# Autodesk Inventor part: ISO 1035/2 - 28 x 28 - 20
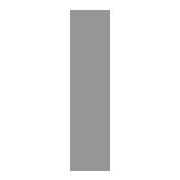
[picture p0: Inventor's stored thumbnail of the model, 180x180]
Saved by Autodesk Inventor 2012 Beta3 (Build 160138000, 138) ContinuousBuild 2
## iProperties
Created: 2010-11
Part Number: ISO 1035/2 - 28 x 28 - 20
Material: Steel, Mild
Description: Hot-rolled steel bars - Part 2: square bars
Document SubType Name: Modeling
Standard: ISO
Designer: Beta-8540w
Standard Revision: First edition 1980-10-15
Standards Organization: ISO
Language: en-US
Size Designation: 28x 28*
Categories: <MemberInstance><Categories><Category DisplayName="Structural Shapes" InternalName="089c4875-fa83-4c05-b084-43b9cc11f5ed" Mnemonic="GRDR"><CategoryParameter Dis
Stock Number: 28x 28*
Density: 7.86 g/cm^3
IsCustomPart: 1
_CCFamilyMember: 180
_CCFamilyDisplayName: ISO 1035/2 - 1980 - Hot-rolled steel bars - Part 2: square bars
_FrameMemberDoc: Frame Member File
_Version: 15.0.0
_GetPNFromCC: 1
G_L: 20.000 mm
G_W: 28.000 mm
G_H: 28.000 mm
Author: Beta-8540w
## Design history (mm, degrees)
node "Start plane"
node "End plane"
sketch "Sketch"
  geometry: L1 (14, -14)-(-14, -14); L2 (-14, -14)-(-14, 14); L3 (-14, 14)-(14, 14); L4 (14, 14)-(14, -14); L5 (-6, 0)-(8, 0); L6 (0, -30)-(0, 40); L7 (0, 54)-(0, -44) reference; L8 (-19.6, 0)-(19.6, 0) reference
  constraints: 12 end point, 2 collinear, 2 parallel, 1 horizontal, 1 perpendicular
  dimensions: "d0" = 28 distance between parallel lines of L3 L1 (= G_W); "d1" = 28 distance between parallel lines of L4 L2 (= G_H); "d4" = 14 distance between parallel lines of L6 L4 (= 0.5 x d1); "d5" = 14 distance between parallel lines of L5 L3 (= 0.5 x d0)
extrude "Body" new body sketch "Sketch" stored distance "d2" = 20 (= G_L); taper "d3" = 0 deg
node "Driven Length"
  sketch "Sketch3"
    geometry: L1 (0, 0)-(10, 0) reference
    constraints: 2 end point, 1 horizontal
  workplane "Work Plane3"
  sketch "Sketch4"
    geometry: L1 (-2, 0)-(12, 0) reference; L2 (-2, 20)-(12, 20) reference
    dimensions: "d9" = 20 distance between parallel lines of L1 L2 (derived)
body "Solid1"
other parameters: "G_W" = 28 [user parameter; used in 1 equation term], "G_H" = 28 [user parameter; used in 1 equation term], "G_L" = 20 (= d9) [user parameter; used in 1 equation term], "G_OFFSET_START" = 0 [user parameter; used in 1 equation term], "G_OFFSET_END" = 0 [user parameter; used in 1 equation term], "d6" = 0 (computed from G_OFFSET_START), "d8" = 90 deg, "AREA" = 78.4 [user parameter]
